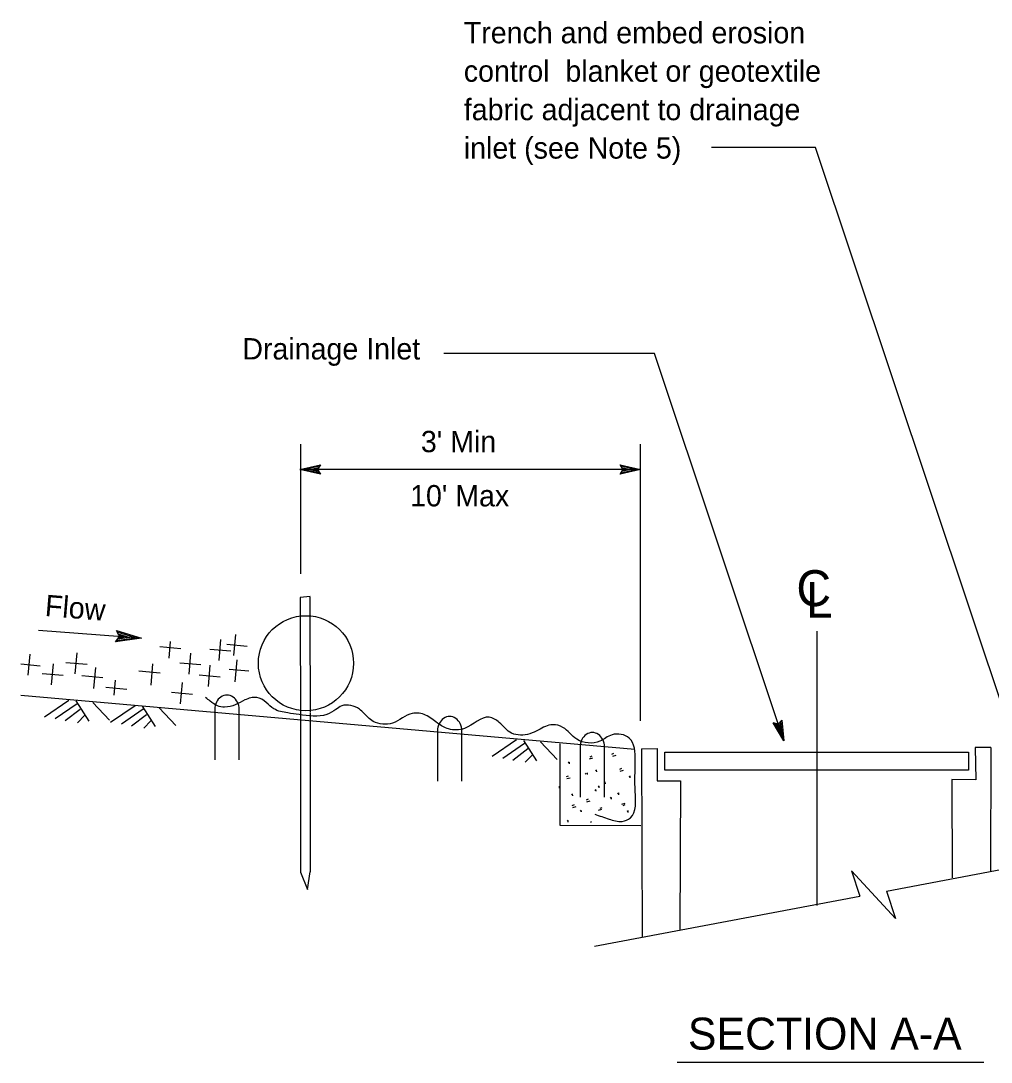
# Model space of a CAD drawing. Extents: x 6708945 to 6710368, y 1871409 to 1872338.
# Drawn here: x 6708958.3 to 6709230.9, y 1871953.1 to 1872245.7 of the extents above; entities that cross this region are included whole.
import ezdxf

# ---------------------------------------------------------------- set-up
doc = ezdxf.new("R2010")
doc.units = 0
for name, color, linetype in [('1 Control', 7, 'Continuous'), ('26 undefined', 7, 'Continuous'), ('57 Undefined', 7, 'Continuous'), ('60 Nongeo Data', 7, 'Continuous')]:
    doc.layers.add(name, color=color, linetype=linetype)

msp = doc.modelspace()

# ---------------------------------------------------------------- linework, layer by layer
at = {"layer": '1 Control'}
for p, q in [((6709042.47, 1872120.91), (6709042.47, 1872120.91)), ((6709126.68, 1872120.91), (6709126.68, 1872120.91)), ((6709036.71, 1872119.63), (6709036.71, 1872119.63)), ((6709042.47, 1872118.34), (6709042.47, 1872118.34)), ((6709126.68, 1872118.35), (6709126.68, 1872118.35)), ((6709132.44, 1872119.63), (6709132.44, 1872119.63)), ((6708985.16, 1872074.36), (6708985.16, 1872074.36)), ((6708984.92, 1872071.17), (6708984.92, 1872071.17)), ((6708992.22, 1872072.21), (6708992.22, 1872072.21)), ((6709012.8, 1872052.25), (6709012.8, 1872038.04)), ((6709019.64, 1872038.04), (6709019.64, 1872052.25)), ((6709075.37, 1872046.24), (6709075.37, 1872032.04)), ((6709082.21, 1872032.04), (6709082.21, 1872046.24)), ((6709115.44, 1872041.74), (6709115.44, 1872027.54)), ((6709122.28, 1872027.54), (6709122.28, 1872041.74))]:
    msp.add_line(p, q, dxfattribs=at)
for points in [[(6709042.47, 1872118.34), (6709036.71, 1872119.63), (6709042.47, 1872120.91), (6709042.26, 1872120.56), (6709038.04, 1872119.63), (6709042.27, 1872118.68), (6709042.06, 1872119.02), (6709039.36, 1872119.63), (6709042.06, 1872120.22), (6709041.85, 1872119.88), (6709040.69, 1872119.63), (6709041.86, 1872119.36), (6709041.7, 1872119.63), (6709042.47, 1872120.91), (6709041.7, 1872119.63)], [(6709126.68, 1872120.91), (6709132.44, 1872119.63), (6709126.68, 1872118.35), (6709126.89, 1872118.69), (6709131.11, 1872119.62), (6709126.89, 1872120.57), (6709127.09, 1872120.23), (6709129.79, 1872119.63), (6709127.09, 1872119.03), (6709127.3, 1872119.37), (6709128.46, 1872119.63), (6709127.29, 1872119.89), (6709127.45, 1872119.63), (6709126.68, 1872118.35), (6709127.45, 1872119.63)], [(6708985.16, 1872074.36), (6708992.22, 1872072.21), (6708984.92, 1872071.17), (6708985.21, 1872071.57), (6708990.55, 1872072.33), (6708985.38, 1872073.92), (6708985.61, 1872073.47), (6708988.91, 1872072.46), (6708985.49, 1872071.98), (6708985.78, 1872072.38), (6708987.26, 1872072.59), (6708985.83, 1872073.03), (6708986, 1872072.69), (6708984.92, 1872071.17), (6708986, 1872072.69)]]:
    msp.add_lwpolyline(points, close=True, dxfattribs=at)
for centre in [(6709016.22, 1872052.25), (6709078.79, 1872046.24), (6709118.86, 1872041.74)]:
    msp.add_ellipse(centre, major_axis=(0, -3.99), ratio=0.857645, start_param=1.570796, end_param=4.712389, dxfattribs=at)
at = {"layer": '26 undefined'}
for p, q in [((6709039.55, 1872083.92), (6709036.83, 1872083.71)), ((6709036.83, 1872083.71), (6709036.83, 1872077.82)), ((6709039.54, 1872083.9), (6709039.54, 1872077.72)), ((6709036.83, 1872077.79), (6709036.84, 1872051.3)), ((6709039.54, 1872077.7), (6709039.55, 1872051.55)), ((6709018.16, 1872067.35), (6709018.68, 1872073.24)), ((6708999.98, 1872066.64), (6709000.39, 1872071.33)), ((6709014.01, 1872065.97), (6709014.53, 1872071.91)), ((6709016.19, 1872070.54), (6709021.87, 1872070.03)), ((6708960.41, 1872061.81), (6708960.93, 1872067.75)), ((6708973.6, 1872062.2), (6708974.13, 1872068.14)), ((6708997.36, 1872069.87), (6709003.3, 1872069.34)), ((6709005.59, 1872062.14), (6709006.11, 1872068.07)), ((6709011.39, 1872069.19), (6709017.32, 1872068.67)), ((6708958.32, 1872064.99), (6708963.73, 1872064.51)), ((6708966.93, 1872059.14), (6708967.45, 1872065.07)), ((6708970.99, 1872065.43), (6708976.92, 1872064.9)), ((6708994.91, 1872059.05), (6708995.44, 1872064.99)), ((6709002.97, 1872065.36), (6709008.9, 1872064.84)), ((6709011, 1872058.69), (6709011.53, 1872064.62)), ((6709018.55, 1872059.95), (6709019.1, 1872066.19)), ((6708964.31, 1872062.36), (6708970.24, 1872061.83)), ((6708975.45, 1872061.74), (6708981.38, 1872061.22)), ((6708978.86, 1872058.12), (6708979.39, 1872064.05)), ((6708991.5, 1872063.08), (6708997.43, 1872062.55)), ((6709008.39, 1872061.91), (6709014.32, 1872061.39)), ((6709016.84, 1872063.57), (6709022.37, 1872063.08)), ((6708982.16, 1872058.49), (6708988.1, 1872057.96)), ((6708984.54, 1872056.27), (6708984.91, 1872060.4)), ((6709003.21, 1872053.84), (6709003.74, 1872059.77)), ((6709000.6, 1872057.06), (6709006.53, 1872056.54)), ((6709036.84, 1872051.37), (6709036.86, 1872006.53)), ((6709039.55, 1872051.33), (6709039.57, 1872006.58)), ((6709118.04, 1872038.33), (6709118.97, 1872038.6)), ((6709118.71, 1872039.06), (6709118.14, 1872038.79)), ((6709124.83, 1872039.86), (6709124.26, 1872039.58)), ((6709124.6, 1872039.13), (6709125.54, 1872039.4)), ((6709112.4, 1872037.4), (6709112.09, 1872037.2)), ((6709112.44, 1872036.95), (6709112.42, 1872037.43)), ((6709120.05, 1872035.16), (6709119.74, 1872034.96)), ((6709120.09, 1872034.71), (6709120.07, 1872035.2)), ((6709127.08, 1872035.64), (6709126.51, 1872035.36)), ((6709126.71, 1872034.91), (6709127.64, 1872035.18)), ((6709112.03, 1872033.51), (6709111.47, 1872033.24)), ((6709111.66, 1872032.78), (6709112.6, 1872033.05)), ((6709117.14, 1872034.21), (6709116.84, 1872034.01)), ((6709117.48, 1872033.91), (6709117.47, 1872034.39)), ((6709129.47, 1872033.48), (6709129.16, 1872033.28)), ((6709129.51, 1872033.03), (6709129.49, 1872033.51)), ((6709109.67, 1872030.14), (6709109.66, 1872030.62)), ((6709119.86, 1872029.69), (6709119.55, 1872029.49)), ((6709119.9, 1872029.24), (6709119.88, 1872029.73)), ((6709120.77, 1872030.63), (6709120.46, 1872030.43)), ((6709120.81, 1872030.18), (6709120.79, 1872030.67)), ((6709122.41, 1872031.91), (6709122.5, 1872031.32)), ((6709113.3, 1872028.39), (6709113, 1872028.19)), ((6709113.34, 1872027.94), (6709113.32, 1872028.42)), ((6709117.71, 1872026.98), (6709117.15, 1872026.71)), ((6709117.34, 1872026.25), (6709118.27, 1872026.52)), ((6709124.19, 1872027.46), (6709123.88, 1872027.26)), ((6709124.23, 1872027.01), (6709124.21, 1872027.5)), ((6709126.24, 1872028.72), (6709125.94, 1872028.52)), ((6709126.28, 1872028.27), (6709126.27, 1872028.75)), ((6709113.72, 1872025.42), (6709113.15, 1872025.15)), ((6709113.35, 1872024.69), (6709114.28, 1872024.96)), ((6709115.74, 1872023.86), (6709115.44, 1872023.66)), ((6709115.78, 1872023.41), (6709115.77, 1872023.9)), ((6709120.59, 1872023.89), (6709121.52, 1872024.16)), ((6709121.56, 1872024.62), (6709120.99, 1872024.35)), ((6709127.18, 1872025.6), (6709128.12, 1872025.87)), ((6709128.01, 1872025.43), (6709127.44, 1872025.15)), ((6709128.9, 1872023.7), (6709128.59, 1872023.5)), ((6709128.94, 1872023.25), (6709128.92, 1872023.73)), ((6709112.08, 1872021.03), (6709111.78, 1872020.83)), ((6709112.12, 1872020.58), (6709112.11, 1872021.06)), ((6709118.65, 1872020.61), (6709118.34, 1872020.41)), ((6709036.87, 1872006.53), (6709038.84, 1872001.59)), ((6709038.84, 1872001.59), (6709039.58, 1872006.58))]:
    msp.add_line(p, q, dxfattribs=at)
for points in [[(6708958.32, 1872056.26), (6709130.78, 1872041.08)], [(6709109.69, 1872042.54), (6709109.73, 1872019.74), (6709132.5, 1872019.57)]]:
    msp.add_lwpolyline(points, dxfattribs=at)
at = {"layer": '57 Undefined'}
for p, q in [((6709181.55, 1872210.09), (6709152.38, 1872210.09)), ((6709235.65, 1872048.14), (6709181.55, 1872210.09)), ((6709136.28, 1872152.27), (6709077.16, 1872152.27)), ((6709172.67, 1872043.36), (6709136.28, 1872152.27)), ((6709037.02, 1872090.35), (6709037.02, 1872126.74)), ((6709132.44, 1872049.02), (6709132.44, 1872126.74)), ((6709132.44, 1872119.63), (6709037.21, 1872119.63)), ((6709181.94, 1872074.25), (6709181.94, 1871997.18)), ((6709201.53, 1872001.18), (6709244.07, 1872009.21)), ((6709119.45, 1871985.69), (6709193.98, 1871999.76)), ((6709142.71, 1871953.12), (6709228.81, 1871953.12))]:
    msp.add_line(p, q, dxfattribs=at)
msp.add_lwpolyline([(6709201.53, 1872001.18), (6709203.99, 1871993.52), (6709191.7, 1872006.84), (6709193.98, 1871999.76)], dxfattribs=at)
at = {"layer": '60 Nongeo Data'}
for p, q in [((6708991.72, 1872072.21), (6708963.29, 1872074.38)), ((6708971.81, 1872054.77), (6708964.93, 1872050.08)), ((6708974.1, 1872053.78), (6708967.95, 1872049.58)), ((6708973.76, 1872054.61), (6708977.46, 1872048.92)), ((6708978.57, 1872054.21), (6708983.22, 1872049.24)), ((6708990.42, 1872053.27), (6708983.54, 1872048.58)), ((6708992.37, 1872053.11), (6708996.06, 1872047.42)), ((6708997.17, 1872052.71), (6709001.83, 1872047.74)), ((6708975.01, 1872052.22), (6708970.78, 1872049.01)), ((6708976.26, 1872050.57), (6708974.23, 1872048.48)), ((6708992.71, 1872052.28), (6708986.56, 1872048.08)), ((6708993.62, 1872050.72), (6708989.39, 1872047.51)), ((6708994.87, 1872049.06), (6708992.83, 1872046.98)), ((6709169.63, 1872048.42), (6709169.63, 1872048.42)), ((6709172.07, 1872049.23), (6709172.07, 1872049.23)), ((6709097.56, 1872043.66), (6709090.68, 1872038.97)), ((6709099.85, 1872042.67), (6709093.7, 1872038.48)), ((6709100.76, 1872041.11), (6709096.53, 1872037.9)), ((6709099.51, 1872043.5), (6709103.2, 1872037.81)), ((6709104.32, 1872043.1), (6709108.97, 1872038.13)), ((6709132.66, 1872041.19), (6709132.85, 1871988.3)), ((6709172.67, 1872043.36), (6709172.67, 1872043.36)), ((6709230.81, 1872041.52), (6709230.69, 1872006.91)), ((6709102.01, 1872039.46), (6709099.98, 1872037.38))]:
    msp.add_line(p, q, dxfattribs=at)
for points in [[(6709172.07, 1872049.23), (6709172.67, 1872043.36), (6709169.63, 1872048.42), (6709170.02, 1872048.33), (6709172.24, 1872044.62), (6709171.81, 1872048.93), (6709171.55, 1872048.63), (6709171.83, 1872045.87), (6709170.41, 1872048.24), (6709170.8, 1872048.16), (6709171.41, 1872047.13), (6709171.29, 1872048.33), (6709171.09, 1872048.09), (6709169.63, 1872048.42), (6709171.09, 1872048.09)], [(6709139.2, 1872040.17), (6709224.53, 1872040.17), (6709224.53, 1872035.14), (6709139.2, 1872035.14)]]:
    msp.add_lwpolyline(points, close=True, dxfattribs=at)
for points in [[(6709132.66, 1872041.19), (6709137.04, 1872041.21), (6709137.03, 1872032.14), (6709143.65, 1872032.18)], [(6709230.81, 1872041.52), (6709226.43, 1872041.54), (6709226.55, 1872032.46), (6709219.83, 1872032.51)], [(6709143.65, 1872032.18), (6709143.43, 1871990.33)], [(6709219.83, 1872032.51), (6709219.97, 1872004.87)]]:
    msp.add_lwpolyline(points, dxfattribs=at)
msp.add_circle((6709038.41, 1872065.2), 13.36, dxfattribs=at)
msp.add_spline([(6709119.54, 1872022.77), (6709123.55, 1872021.43), (6709127.23, 1872020.76), (6709129.57, 1872021.76), (6709130.9, 1872029.12), (6709130.9, 1872037.82), (6709129.23, 1872044.17), (6709124.4, 1872045.09), (6709120.95, 1872043.29), (6709114.52, 1872043.84), (6709110.59, 1872047.19), (6709107.74, 1872047.94), (6709103.69, 1872046.44), (6709101.29, 1872045.39), (6709096.19, 1872045.54), (6709092.73, 1872048.54), (6709089.88, 1872050.04), (6709082.98, 1872046.89), (6709078.48, 1872046.74), (6709075.33, 1872048.39), (6709072.03, 1872050.64), (6709068.28, 1872051.09), (6709062.72, 1872048.39), (6709057.34, 1872048.86), (6709055.82, 1872050.04), (6709053.42, 1872052.29), (6709048.48, 1872053.21), (6709046.85, 1872052.2), (6709044.3, 1872050.82), (6709036.46, 1872050.79), (6709033.31, 1872051.24), (6709029.38, 1872052.41), (6709027.25, 1872054.21), (6709024.58, 1872055.55), (6709021.23, 1872054.88), (6709018.56, 1872053.54), (6709015.55, 1872052.87), (6709013.54, 1872053.21), (6709011.54, 1872054.54), (6709010.2, 1872055.55)], degree=3, dxfattribs=at)

# ---------------------------------------------------------------- texts
at = {"layer": '57 Undefined'}
for s, height, p in [('Trench and embed erosion', 6, (6709082.76, 1872239.37)), ('control  blanket or geotextile ', 6, (6709082.76, 1872228.57)), ('fabric adjacent to drainage', 6, (6709082.76, 1872217.77)), ('inlet (see Note 5)', 6, (6709082.76, 1872206.98)), ('Drainage Inlet', 6, (6709020.55, 1872150.54)), ("3' Min", 6, (6709070.7, 1872124.49)), ("10' Max", 6, (6709067.67, 1872109.26)), ('C', 10.09, (6709176.18, 1872081.25)), ('L', 10.09, (6709178.87, 1872077.97)), ('SECTION A-A', 9, (6709145.71, 1871956.63))]:
    msp.add_text(s, height=height, dxfattribs=at).set_placement(p)
msp.add_text('Flow', height=6, rotation=355.2879, dxfattribs=at).set_placement((6708964.93, 1872078.5))

doc.saveas('drawing.dxf')
